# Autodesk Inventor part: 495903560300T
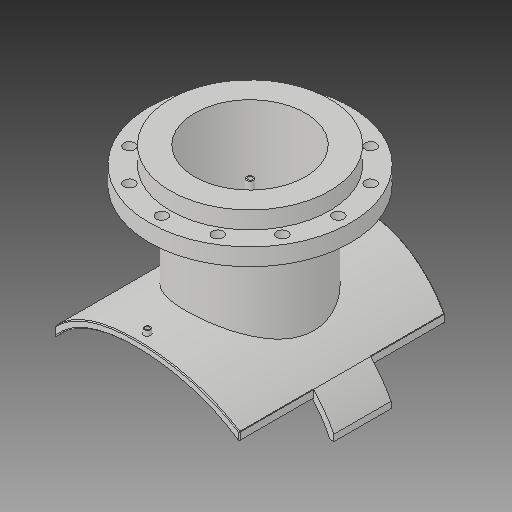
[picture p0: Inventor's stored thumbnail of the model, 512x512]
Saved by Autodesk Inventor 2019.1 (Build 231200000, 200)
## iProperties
Created: 2017-10
Part Number: 495903560300T
Material: Generic
Description: PLASSON FLANGED BRANCH SADDLE 560X300
Document SubType Name: Modeling
Designer: KIM
Mass: 2339.99 g
Surface Area: 3251.55 cm^2
Volume: 2339.99 cm^3
Density: 1 g/cm^3
Appearance: Default
Author: KIM
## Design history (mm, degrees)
derived "495904_495903.ipt"
feature "Solid1::495904_495903.ipt"
feature "Solid2::495904_495903.ipt"
tag "TaggingFeature1"
body "Solid1"
other parameters: "d1" = 15, "d2" = 427.5, "d4" = 0, "d6" = 132.5, "d7" = 0, "d12" = 305.6, "d13" = 14, "d14" = 238.5, "d16" = 5 deg, "d18" = 4, "d19" = 14, "d20" = 0, "d21" = 3, "d22" = 0, "d36" = 238.5, "d38" = 0, "d39" = 2, "d41" = 257, "d43" = 467, "d46" = 296, "d47" = 16, "d48" = 10.4, "d49" = 192.5, "d51" = 571.2, "d53" = 0, "d54" = 26, "d55" = 205, "d57" = 0, "d59" = 360 deg, "d63" = 0, "d66" = 275, "d67" = 15, "d68" = 137.5, "d70" = 0, "d71" = 2, "d72" = 475, "B_" = 475, "H_" = 275, "x_" = 15, "D_" = 16, "DN_" = 257, "D_1" = 467, "s_" = 26
